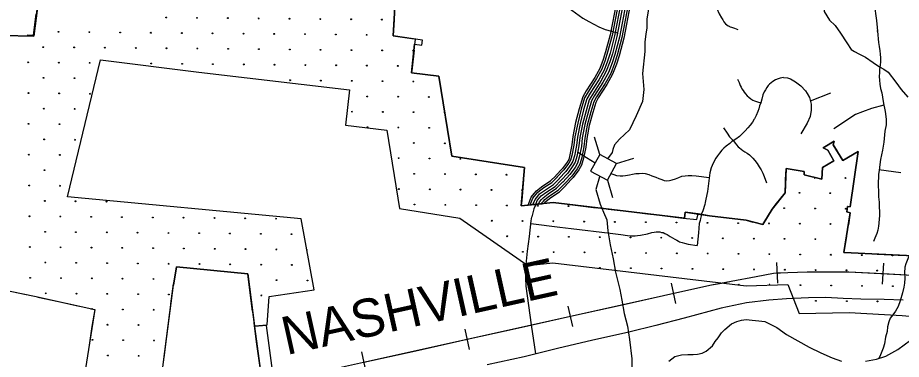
# Model space of a CAD drawing. Extents: x 1788175 to 1969470, y 584502 to 738744.
# Drawn here: x 1798565 to 1809595, y 681239 to 685508 of the extents above; entities that cross this region are included whole.
import ezdxf

# ---------------------------------------------------------------- set-up
doc = ezdxf.new("R2010")
doc.units = 0
for name, color, linetype in [('DESIGN - CONTOURS - Intermediate with optional Text', 7, 'Continuous'), ('DESIGN - EROSION CONTROL - Devices', 7, 'Continuous'), ('DESIGN - SCRATCH - User 1', 7, 'Continuous'), ('DESIGN - TRANSPORTATION - Text', 7, 'Continuous'), ('DESIGN - VEGETATION - Features with Text', 7, 'Continuous'), ('SURVEY - CONTOURS - Index with Text', 7, 'Continuous'), ('SURVEY - CONTOURS - Intermediate with optional Text', 7, 'Continuous'), ('SURVEY - DRAINAGE - Area Shapes', 7, 'Continuous'), ('SURVEY - DRAINAGE - Storm Sewer', 7, 'Continuous'), ('SURVEY - TRANSPORTATION - Roads', 7, 'Continuous'), ('SURVEY - VEGETATION - Features with Text', 7, 'Continuous')]:
    doc.layers.add(name, color=color, linetype=linetype)

msp = doc.modelspace()

# ---------------------------------------------------------------- linework, layer by layer
at = {"layer": 'DESIGN - CONTOURS - Intermediate with optional Text'}
for p, q in [((1808055, 682189), (1808042, 682449)), ((1809360, 682180), (1809375, 682439)), ((1806782, 681937), (1806726, 682191)), ((1805494, 681650), (1805437, 681904)), ((1804205, 681364), (1804149, 681617)), ((1802916, 681077), (1802860, 681331))]:
    msp.add_line(p, q, dxfattribs=at)
for points in [[(1802244, 681061), (1807227, 682169), (1807471, 682215), (1807783, 682274), (1807999, 682316), (1808178, 682325), (1808419, 682334), (1808939, 682334), (1809735, 682289)], [(1807399, 682201), (1807471, 682215), (1807783, 682274), (1807999, 682316), (1808048, 682319)], [(1808048, 682319), (1808178, 682325), (1808419, 682334), (1808708, 682334)], [(1808708, 682334), (1808939, 682334), (1809367, 682310)], [(1809367, 682310), (1809735, 682289), (1810009, 682261), (1810025, 682259)], [(1806754, 682064), (1807227, 682169), (1807399, 682201)], [(1806110, 681920), (1806754, 682064)], [(1805465, 681777), (1806110, 681920)], [(1804821, 681634), (1805465, 681777)], [(1804177, 681490), (1804821, 681634)], [(1803533, 681347), (1804177, 681490)], [(1802888, 681204), (1803533, 681347)]]:
    msp.add_lwpolyline(points, dxfattribs=at)
at = {"layer": 'DESIGN - EROSION CONTROL - Devices'}
for centre in [(1800420, 685510), (1800804, 685506), (1801189, 685503), (1801573, 685499), (1801958, 685495), (1802343, 685491), (1802727, 685488), (1803112, 685484), (1799076, 685331), (1799460, 685327), (1799845, 685323), (1800229, 685320), (1800614, 685316), (1800998, 685312), (1801383, 685308), (1801768, 685305), (1802152, 685301), (1802537, 685297), (1802921, 685294), (1798885, 685140), (1799270, 685137), (1799654, 685133), (1800039, 685129), (1800423, 685126), (1800808, 685122), (1801193, 685118), (1801577, 685114), (1801962, 685111), (1802346, 685107), (1802731, 685103), (1803115, 685099), (1803500, 685096), (1798695, 684950), (1799079, 684946), (1799464, 684943), (1800233, 684935), (1800618, 684931), (1801002, 684928), (1801387, 684924), (1801771, 684920), (1802156, 684916), (1802540, 684913), (1802925, 684909), (1803309, 684905), (1798889, 684756), (1799274, 684752), (1801965, 684726), (1802350, 684722), (1802735, 684719), (1803119, 684715), (1803504, 684711), (1798699, 684566), (1799083, 684562), (1799468, 684558), (1802929, 684524), (1803313, 684521), (1803698, 684517), (1798893, 684371), (1799277, 684368), (1802738, 684334), (1803123, 684330), (1803507, 684327), (1798702, 684181), (1799087, 684177), (1802932, 684140), (1803317, 684136), (1803702, 684132), (1798896, 683987), (1799281, 683983), (1803511, 683942), (1803896, 683938), (1798706, 683796), (1799091, 683793), (1803321, 683752), (1803705, 683748), (1804090, 683744), (1798900, 683602), (1803515, 683557), (1803899, 683554), (1804284, 683550), (1804668, 683546), (1808899, 683505), (1798710, 683412), (1799094, 683408), (1803324, 683367), (1803709, 683363), (1804094, 683360), (1804478, 683356), (1804863, 683352), (1808324, 683319), (1808708, 683315), (1798904, 683218), (1799288, 683214), (1799673, 683210), (1803519, 683173), (1803903, 683169), (1804288, 683165), (1804672, 683162), (1805057, 683158), (1805441, 683154), (1798714, 683027), (1799098, 683024), (1808133, 683128), (1808518, 683124), (1808902, 683121), (1799483, 683020), (1799867, 683016), (1800252, 683012), (1800636, 683009), (1801021, 683005), (1801405, 683001), (1801790, 682997), (1804482, 682971), (1804866, 682968), (1805251, 682964), (1805635, 682960), (1806020, 682956), (1806405, 682953), (1806789, 682949), (1807174, 682945), (1807558, 682941), (1807943, 682938), (1808327, 682934), (1808712, 682930), (1798908, 682833), (1799292, 682829), (1799677, 682826), (1800061, 682822), (1800446, 682818), (1800830, 682815), (1801215, 682811), (1801600, 682807), (1801984, 682803), (1804676, 682777), (1805061, 682773), (1805445, 682770), (1805830, 682766), (1806214, 682762), (1806599, 682759), (1806983, 682755), (1807368, 682751), (1807752, 682747), (1808137, 682744), (1808521, 682740), (1798717, 682643), (1799102, 682639), (1799486, 682635), (1799871, 682632), (1800255, 682628), (1800640, 682624), (1801025, 682620), (1801409, 682617), (1801794, 682613), (1804870, 682583), (1805255, 682579), (1805639, 682576), (1806024, 682572), (1806408, 682568), (1806793, 682564), (1807177, 682561), (1807562, 682557), (1807947, 682553), (1808331, 682549), (1808716, 682546), (1809100, 682542), (1809485, 682538), (1798911, 682449), (1799296, 682445), (1799681, 682441), (1800065, 682437), (1800450, 682434), (1800834, 682430), (1801219, 682426), (1801603, 682422), (1801988, 682419), (1805833, 682381), (1806218, 682378), (1806602, 682374), (1806987, 682370), (1807372, 682366), (1807756, 682363), (1798721, 682258), (1799106, 682254), (1799490, 682251), (1808141, 682359), (1808525, 682355), (1808910, 682352), (1809294, 682348), (1799875, 682247), (1800259, 682243), (1801797, 682228), (1802182, 682225), (1808335, 682165), (1808719, 682161), (1809104, 682157), (1809488, 682154), (1798915, 682064), (1799300, 682060), (1799684, 682057), (1800069, 682053), (1800453, 682049), (1801607, 682038), (1808529, 681971), (1808914, 681967), (1809298, 681963), (1799878, 681862), (1800263, 681859), (1799688, 681672), (1800073, 681668), (1799498, 681482), (1799882, 681478), (1800267, 681474), (1799692, 681287), (1800076, 681284)]:
    msp.add_circle(centre, 5.28, dxfattribs=at)
for centre, start, end in [((1803892, 684323), 62.2599, 316.2879), ((1808514, 683509), 120.9741, 32.1064), ((1808906, 682736), 95.5207, 246.6552), ((1802178, 682609), 154.1461, 226.7923), ((1807566, 682172), 268.6719, 257.7346), ((1807950, 682169), 327.4455, 216.3066), ((1799494, 681866), 25.6101, 129.5559)]:
    msp.add_arc(centre, 5.28, start, end, dxfattribs=at)
at = {"layer": 'DESIGN - SCRATCH - User 1'}
for points in [[(1803254, 685280), (1803284, 685855), (1803489, 685833), (1803519, 686239), (1803536, 686489)], [(1799840, 685973), (1798921, 685942), (1798854, 685955), (1798766, 685278)], [(1798766, 685278), (1798371, 685286), (1798378, 685505), (1798067, 685516), (1798054, 685283), (1797834, 685286), (1797832, 685578), (1797470, 685581), (1797449, 684666), (1796693, 684658), (1797105, 683254), (1797379, 682314), (1798776, 682027), (1799527, 681862), (1799412, 681125), (1800356, 680978), (1800509, 682168)], [(1804851, 683156), (1804893, 683637), (1803984, 683779), (1803821, 684778), (1803482, 684820), (1803520, 685175), (1803609, 685166), (1803619, 685229), (1803254, 685280)], [(1802103, 682994), (1799188, 683270), (1799599, 684981), (1800827, 684827), (1802706, 684608)], [(1802706, 684608), (1802658, 684165), (1803171, 684102), (1803331, 683122), (1804085, 683005), (1804931, 682410)], [(1808879, 682574), (1808957, 683069), (1808916, 683081), (1808921, 683149), (1808958, 683146), (1809055, 683834), (1808865, 683725), (1808744, 683920), (1808755, 683965), (1808620, 683883), (1808678, 683853), (1808753, 683720), (1808612, 683636), (1808601, 683492), (1808380, 683545), (1808382, 683588), (1808156, 683625), (1808145, 683319)], [(1808145, 683319), (1807981, 683116), (1807864, 682924), (1807657, 682977), (1807657, 682976), (1807202, 683033), (1807058, 683057), (1807057, 683057), (1806898, 683079), (1806889, 683005), (1805247, 683199), (1804851, 683156)], [(1801679, 681671), (1801705, 682023), (1802267, 682107), (1802103, 682994)], [(1812261, 681980), (1811129, 682307), (1811069, 682326), (1810777, 682398), (1810554, 682445), (1810473, 682458), (1810307, 682477), (1809659, 682535), (1808968, 682572), (1808879, 682574)], [(1800509, 682168), (1800547, 682395), (1801437, 682306)], [(1804931, 682410), (1805243, 682444), (1807658, 682156), (1808176, 682173), (1808321, 681810)], [(1801437, 682306), (1801523, 681658), (1801679, 681671)], [(1808321, 681810), (1808942, 681823), (1809605, 681787), (1810231, 681730), (1810371, 681715), (1810417, 681707), (1810609, 681667), (1810870, 681602), (1810917, 681588), (1813094, 680961)], [(1801672, 681664), (1801523, 681651), (1801640, 680758)], [(1802469, 680211), (1801954, 680857), (1801745, 681101), (1801672, 681664)]]:
    msp.add_lwpolyline(points, dxfattribs=at)
at = {"layer": 'DESIGN - TRANSPORTATION - Text'}
for points in [[(1806542, 686426), (1806529, 686209), (1806529, 686087), (1806529, 686006), (1806488, 685870), (1806461, 685775), (1806447, 685667), (1806420, 685490), (1806420, 685382), (1806406, 685301), (1806393, 685206), (1806393, 685084), (1806366, 684812), (1806379, 684609), (1806366, 684460), (1806284, 684283), (1806203, 684107), (1806078, 683990), (1806013, 683919), (1805993, 683861), (1805986, 683822), (1805926, 683743)], [(1808495, 686196), (1808563, 686142), (1808618, 686060), (1808618, 685952), (1808604, 685843), (1808604, 685762), (1808618, 685694), (1808631, 685585), (1808699, 685477), (1808767, 685409), (1808835, 685314), (1808916, 685192), (1808970, 685111), (1809011, 685084), (1809065, 685056), (1809147, 685016), (1809241, 684948), (1809323, 684894), (1809377, 684866), (1809431, 684826), (1809526, 684704), (1809594, 684609), (1809674, 684514)], [(1805826, 683518), (1805783, 683363), (1805837, 683176), (1805877, 683076), (1805918, 682981), (1805932, 682845), (1805959, 682669), (1806000, 682493), (1806027, 682330), (1806081, 682113), (1806108, 681977), (1806135, 681814), (1806176, 681652), (1806203, 681489), (1806230, 681245), (1806230, 681055), (1806230, 680865), (1806260, 680643)], [(1809750, 682690), (1809719, 682594), (1809675, 682496), (1809652, 682431), (1809638, 682389), (1809633, 682319), (1809640, 682253), (1809636, 682189), (1809627, 682140), (1809611, 682072), (1809580, 681970), (1809555, 681899), (1809522, 681840), (1809488, 681796), (1809455, 681755), (1809437, 681706), (1809422, 681645), (1809417, 681585), (1809398, 681518), (1809385, 681432), (1809366, 681379), (1809350, 681338), (1809333, 681296), (1809312, 681251)], [(1806691, 681215), (1806767, 681273), (1806849, 681297), (1806929, 681299), (1806997, 681301), (1807051, 681305), (1807107, 681315), (1807157, 681341), (1807239, 681408), (1807273, 681462), (1807308, 681508), (1807352, 681570), (1807390, 681612), (1807475, 681682), (1807543, 681712), (1807599, 681727), (1807629, 681731), (1807660, 681739), (1807731, 681727), (1807818, 681720), (1807893, 681712), (1808039, 681637), (1808163, 681551), (1808445, 681391), (1808589, 681319), (1808732, 681259), (1808846, 681217)], [(1809148, 681216), (1809284, 681242), (1809400, 681280), (1809552, 681364), (1809710, 681478)]]:
    msp.add_lwpolyline(points, dxfattribs=at)
at = {"layer": 'SURVEY - CONTOURS - Index with Text'}
msp.add_lwpolyline([(1809619, 681980), (1809379, 681987), (1809088, 681993), (1808870, 682001), (1808652, 682012), (1808434, 682008), (1808162, 681994), (1807942, 681978), (1807664, 681945), (1807346, 681877), (1806886, 681752), (1806530, 681663), (1806192, 681577), (1805728, 681474), (1805320, 681379), (1804886, 681271), (1804424, 681170)], dxfattribs=at)
at = {"layer": 'SURVEY - CONTOURS - Intermediate with optional Text'}
for points in [[(1806185, 686718), (1806158, 686423), (1806110, 686043), (1806038, 685702), (1805959, 685292), (1805904, 685082), (1805873, 684984), (1805832, 684875), (1805769, 684761), (1805662, 684595), (1805618, 684517), (1805575, 684370), (1805529, 684198), (1805496, 684024), (1805484, 683918), (1805459, 683793), (1805443, 683736), (1805423, 683704), (1805364, 683623), (1805282, 683536), (1805281, 683535)], [(1806211, 686716), (1806183, 686421), (1806135, 686039), (1806063, 685697), (1805984, 685287), (1805929, 685075), (1805898, 684976), (1805856, 684864), (1805791, 684748), (1805684, 684582), (1805642, 684506), (1805600, 684363), (1805555, 684192), (1805521, 684020), (1805509, 683914), (1805484, 683787), (1805467, 683726), (1805444, 683690), (1805384, 683607), (1805301, 683518), (1805300, 683517)], [(1806242, 686713), (1806214, 686417), (1806166, 686033), (1806093, 685691), (1806015, 685280), (1805959, 685066), (1805927, 684966), (1805884, 684851), (1805817, 684732), (1805711, 684566), (1805671, 684494), (1805629, 684355), (1805585, 684185), (1805552, 684015), (1805540, 683910), (1805514, 683780), (1805495, 683714), (1805470, 683672), (1805408, 683587), (1805323, 683497), (1805322, 683496)], [(1806273, 686710), (1806245, 686414), (1806196, 686028), (1806124, 685685), (1806045, 685273), (1805989, 685057), (1805956, 684955), (1805912, 684838), (1805844, 684716), (1805738, 684550), (1805700, 684482), (1805659, 684346), (1805615, 684179), (1805583, 684011), (1805570, 683905), (1805544, 683773), (1805524, 683701), (1805496, 683655), (1805432, 683567), (1805346, 683475), (1805344, 683474)], [(1806273, 686710), (1806245, 686414), (1806196, 686028), (1806124, 685685), (1806045, 685273), (1805989, 685057), (1805956, 684955), (1805912, 684838), (1805844, 684716), (1805738, 684550), (1805700, 684482), (1805659, 684346), (1805615, 684179), (1805583, 684011), (1805570, 683905), (1805544, 683773), (1805524, 683701), (1805496, 683655), (1805432, 683567), (1805346, 683475), (1805344, 683474)], [(1806304, 686707), (1806276, 686410), (1806227, 686023), (1806154, 685679), (1806075, 685266), (1806018, 685049), (1805986, 684945), (1805940, 684825), (1805871, 684700), (1805764, 684534), (1805728, 684470), (1805689, 684338), (1805645, 684172), (1805613, 684006), (1805601, 683900), (1805574, 683766), (1805553, 683689), (1805522, 683638), (1805456, 683547), (1805368, 683454), (1805366, 683452)], [(1806335, 686704), (1806307, 686407), (1806257, 686018), (1806184, 685672), (1806105, 685259), (1806048, 685040), (1806015, 684935), (1805969, 684811), (1805897, 684684), (1805791, 684518), (1805757, 684458), (1805719, 684330), (1805675, 684165), (1805644, 684001), (1805632, 683895), (1805605, 683759), (1805582, 683676), (1805548, 683621), (1805480, 683528), (1805391, 683433), (1805389, 683431)], [(1806359, 686702), (1806331, 686404), (1806282, 686014), (1806209, 685668), (1806130, 685254), (1806072, 685033), (1806038, 684927), (1805991, 684801), (1805918, 684671), (1805812, 684505), (1805780, 684448), (1805743, 684323), (1805700, 684159), (1805668, 683998), (1805656, 683891), (1805629, 683753), (1805604, 683666), (1805568, 683607), (1805499, 683512), (1805408, 683416), (1805406, 683413)], [(1804935, 683165), (1804976, 683266), (1805013, 683313), (1805042, 683346), (1805120, 683405), (1805217, 683468), (1805282, 683534)], [(1804962, 683168), (1804997, 683254), (1805032, 683297), (1805059, 683328), (1805134, 683385), (1805233, 683448), (1805300, 683517)], [(1804997, 683172), (1805024, 683238), (1805056, 683277), (1805080, 683305), (1805152, 683359), (1805253, 683424), (1805322, 683495)], [(1805032, 683175), (1805051, 683222), (1805079, 683257), (1805101, 683282), (1805170, 683334), (1805272, 683400), (1805344, 683474)], [(1805032, 683175), (1805051, 683222), (1805079, 683257), (1805101, 683282), (1805170, 683334), (1805272, 683400), (1805344, 683474)], [(1805067, 683179), (1805078, 683206), (1805103, 683237), (1805123, 683259), (1805187, 683308), (1805292, 683376), (1805366, 683452)], [(1805102, 683183), (1805105, 683190), (1805127, 683217), (1805144, 683236), (1805205, 683283), (1805312, 683352), (1805389, 683431)], [(1805135, 683187), (1805146, 683201), (1805161, 683217), (1805220, 683262), (1805328, 683332), (1805407, 683413)], [(1805032, 683175), (1805009, 683118), (1804984, 683018)], [(1805031, 681307), (1804977, 681669), (1804945, 681913), (1804913, 682153), (1804910, 682257), (1804908, 682381), (1804930, 682591), (1804955, 682773), (1804975, 682970), (1804984, 683018)]]:
    msp.add_lwpolyline(points, dxfattribs=at)
at = {"layer": 'SURVEY - DRAINAGE - Area Shapes'}
for points in [[(1807098, 683041), (1807095, 683033), (1807092, 683015), (1807089, 682998), (1807083, 682974), (1807073, 682935), (1807061, 682821)], [(1804971, 682936), (1805331, 682889), (1805474, 682874)], [(1805474, 682874), (1805961, 682816), (1806094, 682799), (1806177, 682786), (1806214, 682782), (1806247, 682781), (1806271, 682782), (1806303, 682785), (1806338, 682789), (1806428, 682808)], [(1806428, 682808), (1806481, 682826), (1806510, 682829), (1806533, 682831), (1806552, 682832), (1806581, 682831), (1806602, 682826), (1806620, 682822), (1806643, 682813), (1806671, 682798), (1806710, 682776), (1806739, 682758), (1806769, 682740), (1806791, 682728), (1806814, 682716), (1806827, 682709), (1806858, 682700), (1806889, 682689), (1806933, 682678), (1807048, 682663)], [(1807061, 682821), (1807048, 682663)]]:
    msp.add_lwpolyline(points, dxfattribs=at)
at = {"layer": 'SURVEY - DRAINAGE - Storm Sewer'}
for p, q in [((1805830, 683799), (1805764, 684017)), ((1806039, 683687), (1806256, 683752)), ((1805926, 683477), (1805991, 683260))]:
    msp.add_line(p, q, dxfattribs=at)
msp.add_lwpolyline([(1805717, 683590), (1805926, 683477), (1806039, 683687), (1805830, 683799)], close=True, dxfattribs=at)
at = {"layer": 'SURVEY - TRANSPORTATION - Roads'}
for points in [[(1809367, 686814), (1809343, 686672), (1809302, 686446), (1809266, 686093), (1809249, 685861), (1809255, 685681), (1809286, 685471), (1809294, 685385), (1809298, 685341), (1809288, 685340)], [(1806924, 686667), (1806930, 686539), (1806936, 686484), (1806946, 686426), (1806960, 686382), (1807035, 686217), (1807096, 686088), (1807204, 685845), (1807237, 685762), (1807293, 685621), (1807323, 685557), (1807348, 685507), (1807366, 685479), (1807379, 685458), (1807402, 685432), (1807435, 685407), (1807444, 685402), (1807449, 685398), (1807459, 685394), (1807473, 685389), (1807514, 685375), (1807553, 685361)], [(1805235, 686369), (1805221, 686257), (1805211, 686181), (1805203, 686095), (1805199, 686035), (1805198, 685967), (1805202, 685937), (1805209, 685906), (1805236, 685845), (1805254, 685817), (1805281, 685784), (1805328, 685739), (1805436, 685635), (1805619, 685503), (1805695, 685461), (1805817, 685393), (1805899, 685361), (1805977, 685341), (1806054, 685320)], [(1809296, 685341), (1809309, 685197), (1809319, 685149), (1809326, 685092), (1809330, 685054), (1809335, 685007), (1809334, 684961), (1809329, 684912), (1809323, 684864), (1809321, 684821), (1809320, 684775), (1809322, 684728), (1809326, 684678), (1809335, 684623), (1809350, 684569), (1809367, 684462), (1809375, 684413), (1809383, 684378), (1809392, 684337), (1809402, 684272), (1809405, 684237), (1809405, 684171), (1809390, 684090), (1809376, 683951), (1809359, 683853), (1809336, 683734), (1809326, 683673), (1809316, 683600), (1809311, 683552), (1809310, 683511), (1809304, 683456), (1809305, 683401), (1809310, 683344), (1809311, 683270), (1809317, 683203), (1809319, 683146), (1809321, 683083), (1809321, 683034), (1809317, 682993), (1809312, 682942), (1809308, 682902), (1809300, 682855), (1809288, 682813), (1809265, 682754), (1809248, 682710)], [(1808124, 684759), (1808081, 684751), (1808056, 684745), (1808024, 684731), (1807992, 684710), (1807970, 684694), (1807951, 684678), (1807933, 684659), (1807914, 684635), (1807898, 684608), (1807884, 684581), (1807868, 684543), (1807852, 684488), (1807839, 684444), (1807826, 684407), (1807815, 684369), (1807802, 684334), (1807782, 684286), (1807762, 684245), (1807759, 684239), (1807737, 684201), (1807708, 684163), (1807678, 684131), (1807645, 684095), (1807608, 684057), (1807573, 684025), (1807531, 683991), (1807481, 683959), (1807453, 683937), (1807408, 683901), (1807379, 683876), (1807353, 683852), (1807325, 683814), (1807300, 683782), (1807281, 683754), (1807257, 683714), (1807234, 683663), (1807221, 683631), (1807205, 683568), (1807175, 683336), (1807155, 683242), (1807147, 683199), (1807140, 683172), (1807118, 683095), (1807099, 683058)], [(1807549, 684741), (1807563, 684714), (1807570, 684696), (1807584, 684659), (1807595, 684639), (1807605, 684619), (1807620, 684597), (1807633, 684577), (1807651, 684556), (1807670, 684532), (1807691, 684515), (1807717, 684493), (1807740, 684479), (1807763, 684470), (1807786, 684461), (1807798, 684458), (1807839, 684443)], [(1808124, 684759), (1808173, 684755), (1808211, 684743), (1808273, 684706), (1808339, 684658), (1808398, 684593), (1808421, 684562), (1808449, 684511), (1808470, 684426), (1808471, 684352), (1808456, 684274), (1808419, 684192), (1808339, 684056)], [(1808460, 684469), (1808714, 684569)], [(1809376, 684415), (1809222, 684375), (1809110, 684332), (1809022, 684298), (1808752, 684120)], [(1807373, 684133), (1807420, 684064), (1807452, 684021), (1807494, 683973), (1807525, 683936), (1807538, 683918), (1807558, 683894), (1807576, 683880), (1807616, 683848), (1807642, 683833), (1807671, 683815), (1807701, 683796), (1807741, 683754), (1807766, 683722), (1807796, 683684), (1807821, 683644), (1807844, 683606), (1807864, 683565), (1807882, 683524), (1807911, 683443)], [(1805555, 683828), (1805775, 683696)], [(1809313, 683613), (1809588, 683575)], [(1805971, 683561), (1805981, 683556), (1806008, 683548), (1806038, 683537), (1806084, 683534), (1806118, 683534), (1806152, 683536), (1806200, 683544), (1806239, 683553), (1806282, 683560), (1806324, 683563), (1806361, 683567), (1806399, 683562), (1806442, 683548), (1806481, 683534), (1806531, 683514), (1806568, 683498), (1806604, 683486), (1806636, 683474), (1806665, 683468), (1806702, 683472), (1806735, 683480), (1806775, 683496), (1806819, 683513), (1806856, 683526), (1806896, 683532), (1806932, 683536), (1806979, 683536), (1807032, 683532), (1807197, 683510)]]:
    msp.add_lwpolyline(points, dxfattribs=at)
at = {"layer": 'SURVEY - VEGETATION - Features with Text'}
for points in [[(1803286, 687429), (1803259, 687070), (1803577, 687020), (1803550, 686692), (1803519, 686239), (1803489, 685833), (1803284, 685855), (1803254, 685280)], [(1798766, 685278), (1798850, 685955), (1798636, 686013), (1798402, 686043), (1798428, 686208), (1798438, 686332), (1798424, 686424), (1797998, 686335), (1797998, 686188), (1797994, 686071), (1797989, 685963), (1797685, 686004), (1797461, 685750), (1797470, 685581)], [(1797470, 685581), (1797832, 685578), (1797834, 685286), (1798054, 685283), (1798067, 685516), (1798378, 685505), (1798371, 685286), (1798766, 685278)], [(1798762, 685291), (1798796, 685552)], [(1803264, 685485), (1803254, 685280)], [(1798683, 685294), (1798762, 685291)], [(1803254, 685280), (1803525, 685244), (1803523, 685198), (1803520, 685175), (1803482, 684820), (1803821, 684778), (1803984, 683779), (1804893, 683637), (1804851, 683156)], [(1803254, 685280), (1803515, 685245)], [(1803513, 685104), (1803485, 684842)], [(1803485, 684842), (1803482, 684820), (1803723, 684790)], [(1803829, 684728), (1803872, 684467)], [(1803872, 684467), (1803914, 684207)], [(1803938, 684059), (1803981, 683798)], [(1808145, 683319), (1808156, 683625), (1808382, 683588), (1808380, 683545), (1808601, 683492), (1808612, 683636), (1808753, 683720), (1808678, 683853), (1808620, 683883), (1808755, 683965), (1808744, 683920), (1808865, 683725), (1809055, 683834), (1808958, 683146), (1808921, 683149), (1808916, 683081), (1808957, 683069), (1808879, 682574)], [(1808641, 683896), (1808755, 683965), (1808744, 683920), (1808788, 683849)], [(1808733, 683709), (1808753, 683720), (1808678, 683853), (1808620, 683883), (1808641, 683896)], [(1808868, 683727), (1809055, 683834), (1809048, 683786)], [(1803981, 683798), (1803984, 683779), (1804226, 683742)], [(1804374, 683718), (1804635, 683678)], [(1809048, 683786), (1809011, 683525)], [(1804635, 683678), (1804893, 683637), (1804893, 683635)], [(1808145, 683319), (1808154, 683582)], [(1808262, 683608), (1808382, 683588), (1808380, 683545), (1808476, 683522)], [(1808476, 683522), (1808601, 683492), (1808612, 683627)], [(1804880, 683486), (1804857, 683223)], [(1808990, 683376), (1808958, 683146), (1808926, 683148)], [(1797105, 683254), (1797379, 682314), (1798776, 682027), (1799527, 681862), (1799412, 681125), (1800356, 680978), (1800511, 682181)], [(1804851, 683156), (1805247, 683199), (1806889, 683005), (1806896, 683079), (1806898, 683079), (1807202, 683033), (1807657, 682976), (1807657, 682977), (1807864, 682924), (1807981, 683116), (1808145, 683319)], [(1808021, 683166), (1808145, 683319)], [(1804857, 683223), (1804851, 683156)], [(1804851, 683156), (1805113, 683184)], [(1805262, 683197), (1805525, 683166)], [(1805525, 683166), (1805787, 683134)], [(1807877, 682945), (1807981, 683116), (1808021, 683166)], [(1808926, 683148), (1808921, 683149), (1808916, 683081), (1808957, 683069), (1808934, 682921)], [(1805936, 683117), (1806198, 683085)], [(1806198, 683085), (1806460, 683054)], [(1806609, 683036), (1806871, 683005)], [(1806871, 683005), (1807044, 682985), (1807057, 683057), (1807058, 683057), (1807073, 683054)], [(1807221, 683031), (1807483, 682998)], [(1807483, 682998), (1807657, 682976), (1807657, 682977), (1807742, 682955)], [(1808911, 682773), (1808879, 682574)], [(1808879, 682574), (1808968, 682572), (1809659, 682535), (1810307, 682477), (1810473, 682458), (1810554, 682445), (1810777, 682398), (1811069, 682326), (1811129, 682307), (1811425, 682222)], [(1808879, 682574), (1808968, 682572), (1809143, 682563)], [(1809293, 682555), (1809556, 682541)], [(1809556, 682541), (1809659, 682535), (1809820, 682521)], [(1801437, 682306), (1800547, 682395), (1800509, 682168)], [(1800762, 682373), (1800547, 682395), (1800539, 682347)], [(1801025, 682347), (1800762, 682373)], [(1801437, 682306), (1801174, 682332)], [(1801640, 680758), (1801437, 682306)], [(1801464, 682102), (1801437, 682306)], [(1800479, 681934), (1800511, 682181)], [(1800514, 682199), (1800509, 682168)], [(1798413, 682102), (1798671, 682049)], [(1801498, 681840), (1801464, 682102)], [(1798818, 682018), (1799076, 681962)], [(1799076, 681962), (1799334, 681905)], [(1799480, 681872), (1799527, 681862), (1799493, 681648)], [(1800426, 681523), (1800460, 681785)], [(1799493, 681648), (1799453, 681387)], [(1801552, 681430), (1801518, 681692)], [(1800392, 681261), (1800426, 681523)], [(1801586, 681168), (1801552, 681430)]]:
    msp.add_lwpolyline(points, dxfattribs=at)

# ---------------------------------------------------------------- texts
at = {"layer": 'DESIGN - VEGETATION - Features with Text'}
msp.add_text('NASHVILLE', height=475, rotation=12.539, dxfattribs=at).set_placement((1801920, 681291))

doc.saveas('drawing.dxf')
